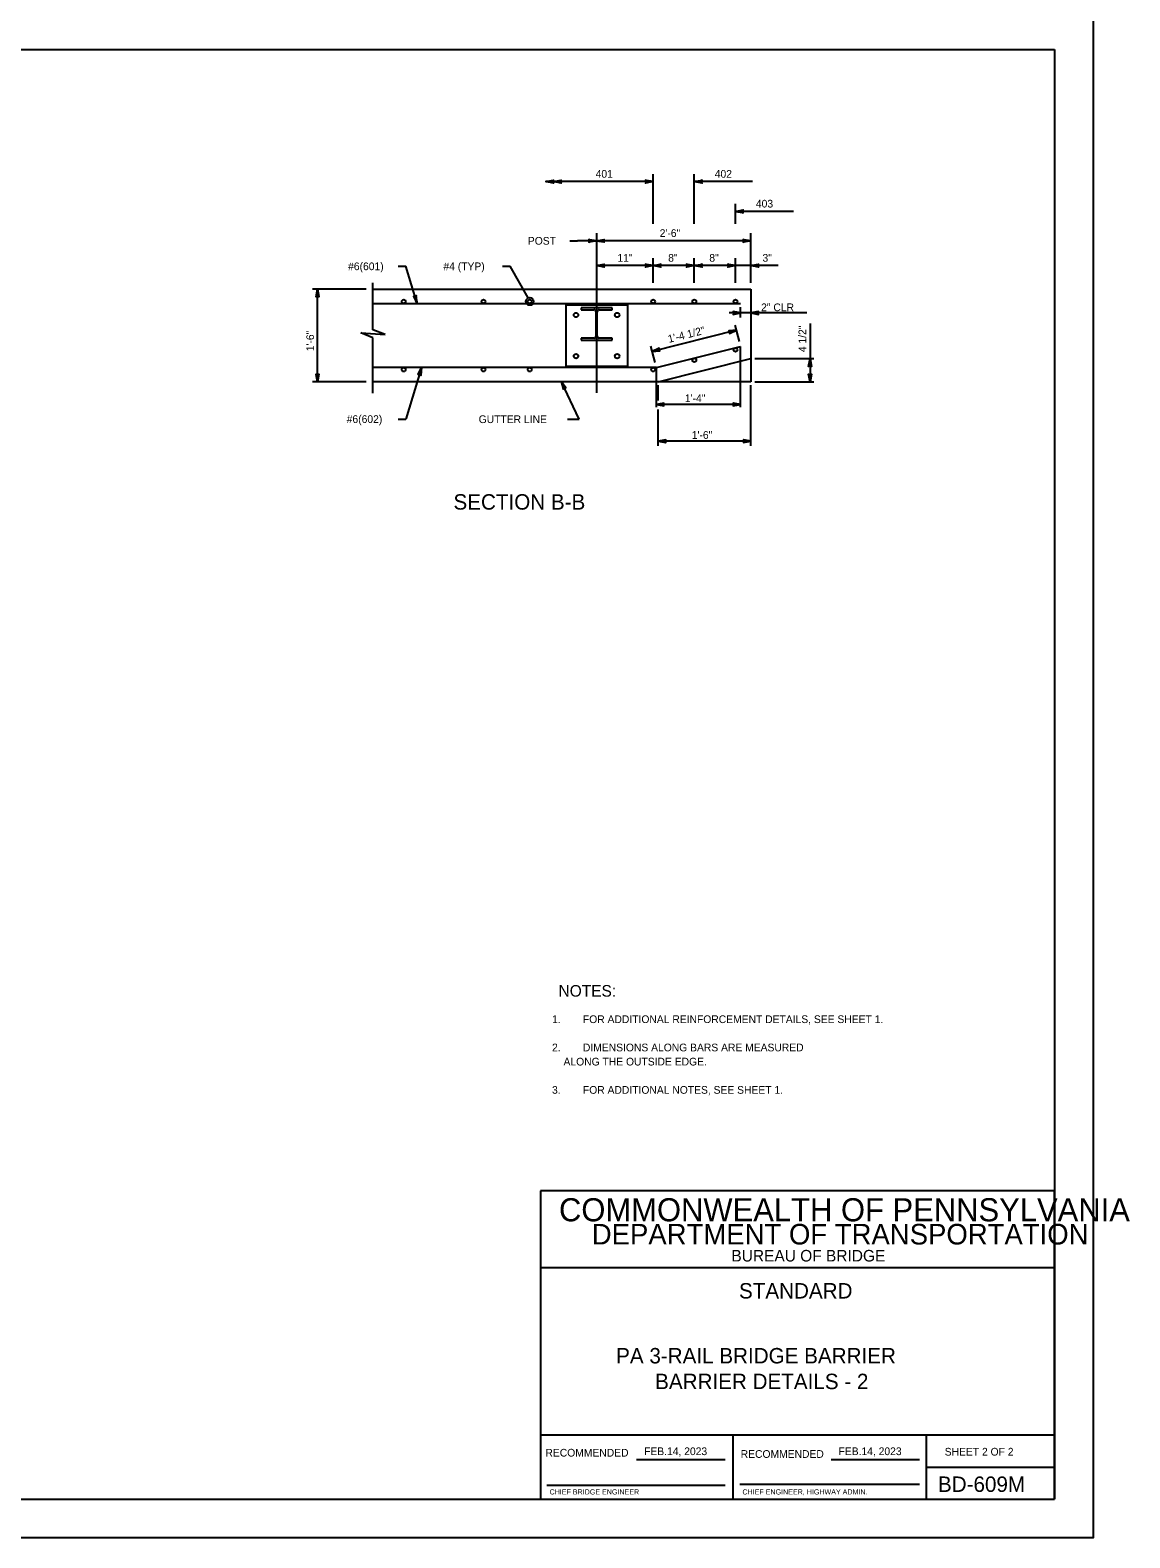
# Model space of a CAD drawing. Extents: x 641054 to 641910, y 298137 to 299325.
# Drawn here: x 641482 to 641910, y 298137 to 298724 of the extents above; entities that cross this region are included whole.
import ezdxf

# ---------------------------------------------------------------- set-up
doc = ezdxf.new("R2010")
doc.units = 0
for name, color, linetype in [('1', 7, 'Continuous'), ('2', 7, 'Continuous'), ('BRDG_BORDER', 7, 'Continuous'), ('DATES', 7, 'Continuous'), ('PLT-BNDY', 7, 'Continuous'), ('S-ABUT', 7, 'Continuous'), ('S-DETL-DIMS', 7, 'Continuous'), ('S-DETL-T120', 7, 'Continuous'), ('S-MISC-CNTR-WT01', 7, 'Continuous'), ('S-WALL-RBAR', 7, 'Continuous'), ('SIGNATORY TITLES', 7, 'Continuous')]:
    doc.layers.add(name, color=color, linetype=linetype)

# ---------------------------------------------------------------- blocks, each defined once
blk = doc.blocks.new('LT')
at = {"layer": 'BRDG_BORDER'}
blk.add_lwpolyline([(0, 0), (-11.184875, -2.097125), (-10.323, -1.5), (-9.878625, -0.75), (-9.75, 0), (-9.878625, 0.75), (-10.323, 1.5), (-11.184875, 2.097125), (0, 0), (-10.323, 1.5), (-9.878625, 0.75), (0, 0), (-9.75, 0), (-9.878625, -0.75), (0, 0), (-10.323, -1.5)], dxfattribs=at)

msp = doc.modelspace()

# ---------------------------------------------------------------- linework, layer by layer
at = {"layer": '1'}
for p, q in [((641690.37, 298617.09), (641714.37, 298617.09)), ((641690.37, 298617.09), (641690.37, 298593.09)), ((641714.37, 298617.09), (641714.37, 298593.09)), ((641708.37, 298615.84), (641696.37, 298615.84)), ((641696.37, 298615.84), (641696.37, 298615.11)), ((641696.37, 298615.11), (641701.34, 298615.11)), ((641702.11, 298614.34), (641702.11, 298604.86)), ((641702.63, 298604.86), (641702.63, 298614.34)), ((641703.4, 298615.11), (641708.37, 298615.11)), ((641708.37, 298615.11), (641708.37, 298615.84)), ((641701.34, 298604.09), (641696.37, 298604.09)), ((641696.37, 298604.09), (641696.37, 298603.34)), ((641696.37, 298603.34), (641708.37, 298603.34)), ((641708.37, 298604.09), (641703.4, 298604.09)), ((641708.37, 298603.34), (641708.37, 298604.09)), ((641714.37, 298593.09), (641690.37, 298593.09))]:
    msp.add_line(p, q, dxfattribs=at)
for centre in [(641694.37, 298613.09), (641710.37, 298613.09), (641694.37, 298597.09), (641710.37, 298597.09)]:
    msp.add_circle(centre, 0.875, dxfattribs=at)
for centre, start, end in [((641701.34, 298614.34), 0, 90), ((641703.4, 298614.34), 90, 180), ((641701.34, 298604.86), 270, 0), ((641703.4, 298604.86), 180, 270)]:
    msp.add_arc(centre, 0.77, start, end, dxfattribs=at)
at = {"layer": '2'}
for p, q in [((641094.49, 298716.38), (641880.49, 298716.38)), ((641880.49, 298716.38), (641880.49, 298152.38)), ((641880.49, 298272.38), (641680.49, 298272.38)), ((641680.49, 298272.38), (641680.49, 298152.38)), ((641880.49, 298152.38), (641880.49, 298272.38)), ((641880.49, 298242.38), (641680.49, 298242.38)), ((641880.49, 298177.38), (641680.49, 298177.38)), ((641755.49, 298152.38), (641755.49, 298177.38)), ((641830.49, 298177.38), (641830.49, 298152.38)), ((641717.94, 298167.88), (641752.35, 298167.88)), ((641793.57, 298167.88), (641827.97, 298167.88)), ((641830.49, 298164.88), (641880.49, 298164.88)), ((641682.99, 298157.88), (641752.35, 298157.88)), ((641758.11, 298158.25), (641827.97, 298158.25)), ((641094.49, 298152.38), (641880.49, 298152.38)), ((641680.49, 298152.38), (641880.49, 298152.38))]:
    msp.add_line(p, q, dxfattribs=at)
at = {"layer": 'PLT-BNDY'}
msp.add_lwpolyline([(641054.49, 298731.38), (641895.49, 298731.38), (641895.49, 298137.38), (641054.49, 298137.38)], close=True, dxfattribs=at)
at = {"layer": 'S-ABUT'}
for p, q in [((641615.41, 298623.09), (641762.37, 298623.09)), ((641762.37, 298623.09), (641762.37, 298587.09)), ((641615.41, 298617.59), (641758.37, 298617.59)), ((641725.6, 298592.59), (641758.37, 298600.78)), ((641726.37, 298587.09), (641762.37, 298596.09)), ((641725.6, 298592.59), (641615.41, 298592.59)), ((641762.37, 298587.09), (641615.41, 298587.09))]:
    msp.add_line(p, q, dxfattribs=at)
at = {"layer": 'S-DETL-DIMS'}
for p, q in [((641724.37, 298664.97), (641682.65, 298664.97)), ((641724.37, 298648.59), (641724.37, 298667.91)), ((641740.37, 298648.59), (641740.37, 298667.91)), ((641762.97, 298664.97), (641740.37, 298664.97)), ((641756.37, 298648.59), (641756.37, 298656.32)), ((641778.97, 298653.38), (641756.37, 298653.38)), ((641691.91, 298641.93), (641694.91, 298641.93)), ((641702.37, 298641.93), (641694.91, 298641.93)), ((641762.37, 298641.93), (641702.87, 298641.93)), ((641762.37, 298625.58), (641762.37, 298644.87)), ((641724.37, 298625.58), (641724.37, 298635.24)), ((641740.37, 298625.58), (641740.37, 298635.24)), ((641756.37, 298625.58), (641756.37, 298635.24)), ((641625.17, 298632.01), (641628.17, 298632.01)), ((641632.61, 298617.59), (641628.17, 298632.01)), ((641665.78, 298632.01), (641668.78, 298632.01)), ((641675.73, 298619.7), (641668.78, 298632.01)), ((641772.97, 298632.3), (641702.37, 298632.3)), ((641612.75, 298623.09), (641591.87, 298623.09)), ((641593.83, 298587.09), (641593.83, 298623.09)), ((641615.41, 298607.34), (641615.41, 298625.6)), ((641784.16, 298613.86), (641753.96, 298613.86)), ((641758.37, 298612.08), (641758.37, 298616.15)), ((641615.41, 298604.21), (641610.72, 298606.12)), ((641610.72, 298606.12), (641620.09, 298605.55)), ((641620.09, 298605.55), (641615.41, 298607.34)), ((641756.79, 298607.12), (641724.02, 298598.93)), ((641757.88, 298602.74), (641756.28, 298609.14)), ((641785.39, 298609.83), (641785.39, 298587.09)), ((641615.41, 298582.64), (641615.41, 298604.21)), ((641725.11, 298594.55), (641723.51, 298600.95)), ((641758.37, 298577.16), (641758.37, 298600.78)), ((641763.87, 298596.09), (641786.89, 298596.09)), ((641634.34, 298592.59), (641628.17, 298572.58)), ((641725.6, 298577.16), (641725.6, 298592.59)), ((641612.75, 298587.09), (641591.87, 298587.09)), ((641695.58, 298572.58), (641688.66, 298587.09)), ((641726.37, 298579.76), (641726.37, 298585.76)), ((641762.37, 298562.14), (641762.37, 298585.76)), ((641763.87, 298587.09), (641786.89, 298587.09)), ((641758.37, 298578.29), (641725.6, 298578.29)), ((641726.37, 298562.14), (641726.37, 298576.34)), ((641625.17, 298572.58), (641628.17, 298572.58)), ((641690.99, 298572.58), (641695.58, 298572.58)), ((641762.37, 298563.99), (641726.37, 298563.99))]:
    msp.add_line(p, q, dxfattribs=at)
for points in [[(641593.83, 298623.09), (641594.38, 298620.18), (641594.3, 298620.29), (641594.22, 298620.4), (641594.13, 298620.46), (641594.03, 298620.52), (641593.93, 298620.54), (641593.83, 298620.55), (641593.74, 298620.54), (641593.64, 298620.52), (641593.54, 298620.46), (641593.44, 298620.4), (641593.37, 298620.29), (641593.29, 298620.18), (641593.83, 298623.09), (641593.37, 298620.29), (641593.44, 298620.4), (641593.83, 298623.09), (641593.54, 298620.46), (641593.64, 298620.52), (641593.83, 298623.09), (641593.74, 298620.54), (641593.83, 298620.55), (641593.83, 298623.09), (641593.93, 298620.54), (641594.03, 298620.52), (641593.83, 298623.09), (641594.13, 298620.46), (641594.22, 298620.4), (641593.83, 298623.09), (641594.3, 298620.29)], [(641758.37, 298613.86), (641755.46, 298614.41), (641755.57, 298614.33), (641755.68, 298614.25), (641755.74, 298614.15), (641755.8, 298614.06), (641755.82, 298613.96), (641755.83, 298613.86), (641755.82, 298613.76), (641755.8, 298613.66), (641755.74, 298613.57), (641755.68, 298613.47), (641755.57, 298613.39), (641755.46, 298613.31), (641758.37, 298613.86), (641755.57, 298613.39), (641755.68, 298613.47), (641758.37, 298613.86), (641755.74, 298613.57), (641755.8, 298613.66), (641758.37, 298613.86), (641755.82, 298613.76), (641755.83, 298613.86), (641758.37, 298613.86), (641755.82, 298613.96), (641755.8, 298614.06), (641758.37, 298613.86), (641755.74, 298614.15), (641755.68, 298614.25), (641758.37, 298613.86), (641755.57, 298614.33)], [(641762.37, 298613.86), (641765.28, 298613.31), (641765.17, 298613.39), (641765.06, 298613.47), (641765, 298613.57), (641764.94, 298613.66), (641764.93, 298613.76), (641764.91, 298613.86), (641764.93, 298613.96), (641764.94, 298614.06), (641765, 298614.15), (641765.06, 298614.25), (641765.17, 298614.33), (641765.28, 298614.41), (641762.37, 298613.86), (641765.17, 298614.33), (641765.06, 298614.25), (641762.37, 298613.86), (641765, 298614.15), (641764.94, 298614.06), (641762.37, 298613.86), (641764.93, 298613.96), (641764.91, 298613.86), (641762.37, 298613.86), (641764.93, 298613.76), (641764.94, 298613.66), (641762.37, 298613.86), (641765, 298613.57), (641765.06, 298613.47), (641762.37, 298613.86), (641765.17, 298613.39)], [(641756.79, 298607.12), (641753.83, 298606.94), (641753.96, 298606.9), (641754.08, 298606.85), (641754.16, 298606.77), (641754.24, 298606.69), (641754.28, 298606.6), (641754.32, 298606.5), (641754.33, 298606.41), (641754.34, 298606.31), (641754.31, 298606.2), (641754.27, 298606.09), (641754.18, 298605.99), (641754.09, 298605.88), (641756.79, 298607.12), (641754.18, 298605.99), (641754.27, 298606.09), (641756.79, 298607.12), (641754.31, 298606.2), (641754.34, 298606.31), (641756.79, 298607.12), (641754.33, 298606.41), (641754.32, 298606.5), (641756.79, 298607.12), (641754.28, 298606.6), (641754.24, 298606.69), (641756.79, 298607.12), (641754.16, 298606.77), (641754.08, 298606.85), (641756.79, 298607.12), (641753.96, 298606.9)], [(641724.02, 298598.93), (641726.98, 298599.1), (641726.85, 298599.15), (641726.72, 298599.2), (641726.64, 298599.28), (641726.56, 298599.36), (641726.52, 298599.45), (641726.48, 298599.54), (641726.47, 298599.64), (641726.47, 298599.74), (641726.5, 298599.85), (641726.53, 298599.96), (641726.62, 298600.06), (641726.71, 298600.16), (641724.02, 298598.93), (641726.62, 298600.06), (641726.53, 298599.96), (641724.02, 298598.93), (641726.5, 298599.85), (641726.47, 298599.74), (641724.02, 298598.93), (641726.47, 298599.64), (641726.48, 298599.54), (641724.02, 298598.93), (641726.52, 298599.45), (641726.56, 298599.36), (641724.02, 298598.93), (641726.64, 298599.28), (641726.72, 298599.2), (641724.02, 298598.93), (641726.85, 298599.15)], [(641593.83, 298587.09), (641593.29, 298590), (641593.37, 298589.89), (641593.44, 298589.78), (641593.54, 298589.72), (641593.64, 298589.66), (641593.74, 298589.65), (641593.83, 298589.63), (641593.93, 298589.65), (641594.03, 298589.66), (641594.13, 298589.72), (641594.22, 298589.78), (641594.3, 298589.89), (641594.38, 298590), (641593.83, 298587.09), (641594.3, 298589.89), (641594.22, 298589.78), (641593.83, 298587.09), (641594.13, 298589.72), (641594.03, 298589.66), (641593.83, 298587.09), (641593.93, 298589.65), (641593.83, 298589.63), (641593.83, 298587.09), (641593.74, 298589.65), (641593.64, 298589.66), (641593.83, 298587.09), (641593.54, 298589.72), (641593.44, 298589.78), (641593.83, 298587.09), (641593.37, 298589.89)], [(641688.66, 298587.09), (641689.42, 298584.23), (641689.44, 298584.36), (641689.46, 298584.5), (641689.53, 298584.59), (641689.59, 298584.69), (641689.67, 298584.74), (641689.75, 298584.8), (641689.85, 298584.83), (641689.94, 298584.85), (641690.06, 298584.84), (641690.17, 298584.83), (641690.29, 298584.77), (641690.41, 298584.7), (641688.66, 298587.09), (641690.29, 298584.77), (641690.17, 298584.83), (641688.66, 298587.09), (641690.06, 298584.84), (641689.94, 298584.85), (641688.66, 298587.09), (641689.85, 298584.83), (641689.75, 298584.8), (641688.66, 298587.09), (641689.67, 298584.74), (641689.59, 298584.69), (641688.66, 298587.09), (641689.53, 298584.59), (641689.46, 298584.5), (641688.66, 298587.09), (641689.44, 298584.36)], [(641725.6, 298578.29), (641728.51, 298577.74), (641728.4, 298577.82), (641728.29, 298577.9), (641728.23, 298577.99), (641728.17, 298578.09), (641728.16, 298578.19), (641728.14, 298578.29), (641728.16, 298578.39), (641728.17, 298578.48), (641728.23, 298578.58), (641728.29, 298578.68), (641728.4, 298578.76), (641728.51, 298578.83), (641725.6, 298578.29), (641728.4, 298578.76), (641728.29, 298578.68), (641725.6, 298578.29), (641728.23, 298578.58), (641728.17, 298578.48), (641725.6, 298578.29), (641728.16, 298578.39), (641728.14, 298578.29), (641725.6, 298578.29), (641728.16, 298578.19), (641728.17, 298578.09), (641725.6, 298578.29), (641728.23, 298577.99), (641728.29, 298577.9), (641725.6, 298578.29), (641728.4, 298577.82)], [(641758.37, 298578.29), (641755.46, 298578.83), (641755.57, 298578.76), (641755.68, 298578.68), (641755.74, 298578.58), (641755.8, 298578.48), (641755.82, 298578.39), (641755.83, 298578.29), (641755.82, 298578.19), (641755.8, 298578.09), (641755.74, 298577.99), (641755.68, 298577.9), (641755.57, 298577.82), (641755.46, 298577.74), (641758.37, 298578.29), (641755.57, 298577.82), (641755.68, 298577.9), (641758.37, 298578.29), (641755.74, 298577.99), (641755.8, 298578.09), (641758.37, 298578.29), (641755.82, 298578.19), (641755.83, 298578.29), (641758.37, 298578.29), (641755.82, 298578.39), (641755.8, 298578.48), (641758.37, 298578.29), (641755.74, 298578.58), (641755.68, 298578.68), (641758.37, 298578.29), (641755.57, 298578.76)], [(641726.37, 298563.99), (641729.28, 298563.44), (641729.17, 298563.52), (641729.06, 298563.6), (641729, 298563.7), (641728.94, 298563.8), (641728.93, 298563.89), (641728.91, 298563.99), (641728.93, 298564.09), (641728.94, 298564.19), (641729, 298564.28), (641729.06, 298564.38), (641729.17, 298564.46), (641729.28, 298564.54), (641726.37, 298563.99), (641729.17, 298564.46), (641729.06, 298564.38), (641726.37, 298563.99), (641729, 298564.28), (641728.94, 298564.19), (641726.37, 298563.99), (641728.93, 298564.09), (641728.91, 298563.99), (641726.37, 298563.99), (641728.93, 298563.89), (641728.94, 298563.8), (641726.37, 298563.99), (641729, 298563.7), (641729.06, 298563.6), (641726.37, 298563.99), (641729.17, 298563.52)], [(641762.37, 298563.99), (641759.46, 298564.54), (641759.57, 298564.46), (641759.68, 298564.38), (641759.74, 298564.28), (641759.8, 298564.19), (641759.82, 298564.09), (641759.83, 298563.99), (641759.82, 298563.89), (641759.8, 298563.8), (641759.74, 298563.7), (641759.68, 298563.6), (641759.57, 298563.52), (641759.46, 298563.44), (641762.37, 298563.99), (641759.57, 298563.52), (641759.68, 298563.6), (641762.37, 298563.99), (641759.74, 298563.7), (641759.8, 298563.8), (641762.37, 298563.99), (641759.82, 298563.89), (641759.83, 298563.99), (641762.37, 298563.99), (641759.82, 298564.09), (641759.8, 298564.19), (641762.37, 298563.99), (641759.74, 298564.28), (641759.68, 298564.38), (641762.37, 298563.99), (641759.57, 298564.46)]]:
    msp.add_lwpolyline(points, dxfattribs=at)
msp.add_circle((641676.37, 298618.34), 1.5, dxfattribs=at)
at = {"layer": 'S-MISC-CNTR-WT01'}
msp.add_line((641702.37, 298644.87), (641702.37, 298582.83), dxfattribs=at)
at = {"layer": 'S-WALL-RBAR'}
for centre in [(641627.37, 298618.34), (641658.37, 298618.34), (641676.37, 298618.34), (641724.37, 298618.34), (641740.37, 298618.34), (641756.37, 298618.34), (641756.37, 298599.51), (641740.37, 298595.51), (641627.37, 298591.84), (641658.37, 298591.84), (641676.37, 298591.84), (641724.37, 298591.84)]:
    msp.add_circle(centre, 0.75, dxfattribs=at)

# ---------------------------------------------------------------- block references
at = {"layer": 'S-DETL-DIMS'}
for p, xscale, yscale, rotation in [((641682.65, 298664.97), 0.26819958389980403, 0.26820457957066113, 180), ((641685.65, 298664.97), 0.26819958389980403, 0.26820457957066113, 180), ((641740.37, 298664.97), 0.26819958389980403, 0.26820457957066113, 180), ((641756.37, 298653.38), 0.26819958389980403, 0.26820457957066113, 180), ((641702.37, 298641.93), 0.26819958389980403, 0.26820457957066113, 180), ((641702.37, 298632.3), 0.26819958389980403, 0.26820457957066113, 180), ((641724.37, 298632.3), 0.26819958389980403, 0.26820457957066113, 180), ((641740.37, 298632.3), 0.26819958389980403, 0.26820457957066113, 180), ((641762.37, 298632.3), 0.26819958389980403, 0.26820457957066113, 180), ((641632.61, 298617.59), 0.26819958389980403, -0.26820457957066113, -72.87291174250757), ((641785.39, 298596.09), 0.26819958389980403, 0.26820457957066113, 90), ((641634.34, 298592.59), 0.2681995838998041, 0.26820457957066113, 72.87291174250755), ((641785.39, 298587.09), 0.26819958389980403, 0.26820457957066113, -90)]:
    msp.add_blockref('LT', p, dxfattribs=dict(at, xscale=xscale, yscale=yscale, rotation=rotation))
for p, xscale, yscale in [((641724.37, 298664.97), 0.26819958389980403, 0.26820457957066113), ((641702.37, 298641.93), 0.2683336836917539, 0.26833868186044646), ((641762.37, 298641.93), 0.26819958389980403, 0.26820457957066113), ((641724.37, 298632.3), 0.26819958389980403, 0.26820457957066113), ((641740.37, 298632.3), 0.26819958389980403, 0.26820457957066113), ((641756.37, 298632.3), 0.26819958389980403, 0.26820457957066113)]:
    msp.add_blockref('LT', p, dxfattribs=dict(at, xscale=xscale, yscale=yscale))

# ---------------------------------------------------------------- texts
at = {"layer": '2'}
for s, height, p in [('SECTION B-B', 6, (641646.71, 298537.36)), ('NOTES:', 4.5, (641687.57, 298347.91)), ('1.', 3, (641685.05, 298337.63)), ('FOR ADDITIONAL REINFORCEMENT DETAILS, SEE SHEET 1.', 3, (641697.05, 298337.63)), ('2.', 3, (641685.05, 298326.63)), ('DIMENSIONS ALONG BARS ARE MEASURED', 3, (641697.05, 298326.63)), ('    ALONG THE OUTSIDE EDGE.', 3, (641685.05, 298321.13)), ('3.', 3, (641685.05, 298310.13)), ('FOR ADDITIONAL NOTES, SEE SHEET 1.', 3, (641697.05, 298310.13)), ('COMMONWEALTH OF PENNSYLVANIA', 9, (641687.74, 298260.5)), ('DEPARTMENT OF TRANSPORTATION', 8.0002, (641700.49, 298251.5)), ('BUREAU OF BRIDGE', 4.5, (641754.79, 298244.88)), ('STANDARD', 6, (641757.74, 298230.48)), ('PA 3-RAIL BRIDGE BARRIER', 6, (641709.96, 298205.23)), ('BARRIER DETAILS - 2', 6, (641725.13, 298195.23)), ('SHEET 2 OF 2', 3, (641837.74, 298169.38)), ('BD-609M', 6, (641835.11, 298155.25))]:
    msp.add_text(s, height=height, dxfattribs=at).set_placement(p)
for p in [(641682.47, 298168.99), (641758.4, 298168.5)]:
    msp.add_text('RECOMMENDED', height=3, rotation=360, dxfattribs=at).set_placement(p)
at = {"layer": 'DATES'}
for p in [(641720.83, 298169.56), (641796.44, 298169.56)]:
    msp.add_text('FEB.14, 2023', height=3, dxfattribs=at).set_placement(p)
at = {"layer": 'S-DETL-DIMS'}
for s, height, p in [('401', 3, (641702, 298666.47)), ('402', 3, (641748.31, 298666.47)), ('403', 3, (641764.31, 298654.88)), ('2\'-6"', 3, (641726.9, 298643.43)), ('  POST', 3.001, (641673.41, 298640.43)), ('11"', 3, (641710.48, 298633.8)), ('8"', 3, (641730.2, 298633.8)), ('8"', 3, (641746.2, 298633.8)), ('3"', 3, (641766.88, 298633.8)), ('#6(601)', 3, (641605.74, 298630.51)), ('#4 (TYP)', 3, (641642.81, 298630.51)), ('#6(602)', 3, (641605.2, 298571.08))]:
    msp.add_text(s, height=height, dxfattribs=at).set_placement(p)
msp.add_text('4 1/2"', height=3, rotation=90, dxfattribs=at).set_placement((641783.89, 298598.62))
at = {"layer": 'S-DETL-T120'}
for s, p in [('2" CLR', (641766.34, 298614.56)), ('1\'-4"', (641736.69, 298579.2)), ('GUTTER LINE', (641656.52, 298571.03)), ('1\'-6"', (641739.37, 298564.9))]:
    msp.add_text(s, height=3, dxfattribs=at).set_placement(p)
for s, rotation, p in [('1\'-6"', 90, (641592.49, 298598.97)), ('1\'-4 1/2"', 14.03624, (641730.5, 298602.22))]:
    msp.add_text(s, height=3, rotation=rotation, dxfattribs=at).set_placement(p)
at = {"layer": 'SIGNATORY TITLES'}
for s, p in [('CHIEF BRIDGE ENGINEER', (641684.08, 298154.25)), ('CHIEF ENGINEER, HIGHWAY ADMIN.', (641759.08, 298154.25))]:
    msp.add_text(s, height=2, dxfattribs=at).set_placement(p)

doc.saveas('drawing.dxf')
